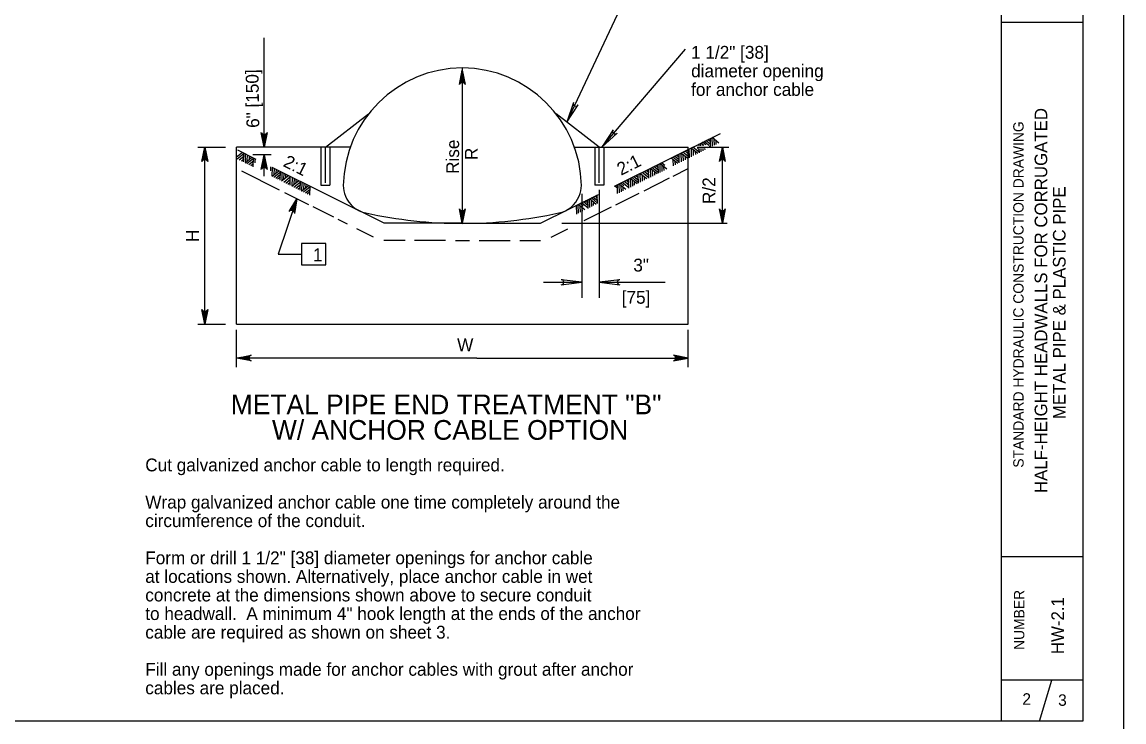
# Model space of a CAD drawing. Extents: x 1083.1 to 1117.1, y 675.4 to 741.4.
# Drawn here: x 1103.72 to 1117.13, y 697.84 to 706.36 of the extents above; entities that cross this region are included whole.
import ezdxf

# ---------------------------------------------------------------- set-up
doc = ezdxf.new("R2010")
doc.units = 0
doc.layers.add('Level 1', color=7, linetype='Continuous')
doc.layers.add('Level 44', color=7, linetype='Continuous')

msp = doc.modelspace()

# ---------------------------------------------------------------- linework, layer by layer
at = {"layer": 'Level 1'}
for p, q in [((1115.636, 697.854), (1115.636, 718.854)), ((1110.352, 705.14), (1111.104, 706.741)), ((1116.626, 706.354), (1115.636, 706.354)), ((1106.67, 704.838), (1106.67, 706.164)), ((1110.775, 704.838), (1111.792, 706.029)), ((1109.054, 705.612), (1109.079, 705.774)), ((1109.065, 705.618), (1109.079, 705.774)), ((1109.079, 705.8), (1109.079, 704.479)), ((1109.079, 705.62), (1109.079, 705.774)), ((1109.091, 705.619), (1109.079, 705.774)), ((1109.102, 705.613), (1109.079, 705.774)), ((1107.413, 704.838), (1107.938, 705.241)), ((1110.745, 704.838), (1110.22, 705.241)), ((1106.647, 704.998), (1106.67, 704.838)), ((1106.658, 704.993), (1106.67, 704.838)), ((1106.695, 705), (1106.67, 704.838)), ((1106.684, 704.994), (1106.67, 704.838)), ((1106.67, 704.991), (1106.67, 704.838)), ((1110.931, 704.36), (1112.219, 705.004)), ((1105.862, 704.838), (1106.2, 704.838)), ((1105.923, 704.676), (1105.948, 704.838)), ((1105.933, 704.682), (1105.948, 704.838)), ((1105.948, 703.621), (1105.948, 704.838)), ((1105.948, 704.685), (1105.948, 704.838)), ((1105.959, 704.683), (1105.948, 704.838)), ((1105.97, 704.678), (1105.948, 704.838)), ((1106.332, 702.685), (1106.332, 704.838)), ((1107.716, 704.838), (1106.332, 704.838)), ((1107.358, 704.838), (1107.358, 704.375)), ((1107.413, 704.404), (1107.413, 704.838)), ((1107.468, 704.838), (1107.468, 704.375)), ((1110.441, 704.838), (1111.826, 704.838)), ((1110.69, 704.838), (1110.69, 704.375)), ((1110.745, 704.404), (1110.745, 704.838)), ((1110.8, 704.838), (1110.8, 704.375)), ((1111.826, 702.685), (1111.826, 704.838)), ((1111.902, 704.819), (1111.882, 704.836)), ((1111.937, 704.853), (1111.929, 704.859)), ((1111.934, 704.838), (1112.32, 704.838)), ((1111.96, 704.854), (1111.959, 704.875)), ((1112.015, 704.855), (1111.979, 704.884)), ((1111.982, 704.854), (1111.981, 704.882)), ((1112.039, 704.864), (1112, 704.895)), ((1112.005, 704.855), (1112.005, 704.863)), ((1112.079, 704.856), (1112.019, 704.904)), ((1112.099, 704.87), (1112.042, 704.916)), ((1112.098, 704.903), (1112.066, 704.928)), ((1112.1, 704.84), (1112.086, 704.85)), ((1112.099, 704.857), (1112.096, 704.943)), ((1112.1, 704.836), (1112.099, 704.851)), ((1112.199, 704.886), (1112.116, 704.952)), ((1112.121, 704.857), (1112.118, 704.95)), ((1112.121, 704.847), (1112.121, 704.852)), ((1112.145, 704.859), (1112.142, 704.931)), ((1112.168, 704.87), (1112.166, 704.912)), ((1112.217, 704.676), (1112.242, 704.838)), ((1112.227, 704.682), (1112.242, 704.838)), ((1112.242, 704.209), (1112.242, 704.838)), ((1112.242, 704.685), (1112.242, 704.838)), ((1112.253, 704.683), (1112.242, 704.838)), ((1112.264, 704.678), (1112.242, 704.838)), ((1106.332, 704.718), (1106.402, 704.773)), ((1106.342, 704.695), (1106.421, 704.758)), ((1106.573, 704.687), (1106.349, 704.799)), ((1106.367, 704.682), (1106.421, 704.725)), ((1106.419, 704.656), (1106.422, 704.763)), ((1106.437, 704.647), (1106.521, 704.714)), ((1106.44, 704.649), (1106.443, 704.752)), ((1106.459, 704.636), (1106.539, 704.701)), ((1106.464, 704.668), (1106.466, 704.741)), ((1106.489, 704.688), (1106.49, 704.729)), ((1106.753, 704.742), (1106.531, 704.742)), ((1106.537, 704.597), (1106.54, 704.704)), ((1106.56, 704.644), (1106.561, 704.693)), ((1106.645, 704.58), (1106.67, 704.742)), ((1106.655, 704.586), (1106.67, 704.742)), ((1106.67, 704.483), (1106.67, 704.742)), ((1106.67, 704.589), (1106.67, 704.742)), ((1106.681, 704.587), (1106.67, 704.742)), ((1106.692, 704.581), (1106.67, 704.742)), ((1111.702, 704.638), (1111.619, 704.704)), ((1111.679, 704.684), (1111.64, 704.715)), ((1111.717, 704.681), (1111.661, 704.725)), ((1111.717, 704.712), (1111.685, 704.737)), ((1111.718, 704.646), (1111.715, 704.752)), ((1111.821, 704.697), (1111.738, 704.763)), ((1111.744, 704.659), (1111.741, 704.76)), ((1111.844, 704.711), (1111.763, 704.776)), ((1111.769, 704.671), (1111.767, 704.74)), ((1111.842, 704.744), (1111.788, 704.788)), ((1111.793, 704.683), (1111.792, 704.72)), ((1111.841, 704.775), (1111.811, 704.8)), ((1111.844, 704.708), (1111.84, 704.815)), ((1111.944, 704.759), (1111.861, 704.825)), ((1111.868, 704.72), (1111.865, 704.822)), ((1111.892, 704.733), (1111.89, 704.802)), ((1111.963, 704.771), (1111.903, 704.819)), ((1111.918, 704.745), (1111.916, 704.781)), ((1111.962, 704.802), (1111.938, 704.821)), ((1111.963, 704.768), (1111.961, 704.82)), ((1111.984, 704.779), (1111.983, 704.82)), ((1112.008, 704.79), (1112.007, 704.819)), ((1112.031, 704.802), (1112.03, 704.819)), ((1112.062, 704.818), (1112.06, 704.819)), ((1106.392, 704.67), (1106.42, 704.692)), ((1106.482, 704.625), (1106.539, 704.67)), ((1106.505, 704.613), (1106.538, 704.639)), ((1106.751, 704.548), (1106.752, 704.598)), ((1108.128, 703.91), (1106.768, 704.59)), ((1106.768, 704.485), (1106.771, 704.588)), ((1106.792, 704.504), (1106.794, 704.577)), ((1106.817, 704.524), (1106.818, 704.565)), ((1111.347, 704.46), (1111.343, 704.566)), ((1111.447, 704.51), (1111.364, 704.576)), ((1111.371, 704.472), (1111.368, 704.573)), ((1111.466, 704.523), (1111.385, 704.587)), ((1111.465, 704.553), (1111.408, 704.599)), ((1111.464, 704.586), (1111.432, 704.611)), ((1111.466, 704.519), (1111.462, 704.626)), ((1111.565, 704.569), (1111.482, 704.636)), ((1111.487, 704.53), (1111.484, 704.633)), ((1111.542, 704.615), (1111.503, 704.646)), ((1111.511, 704.542), (1111.508, 704.614)), ((1111.534, 704.553), (1111.532, 704.595)), ((1111.642, 704.483), (1111.826, 704.575)), ((1111.648, 704.61), (1111.645, 704.683)), ((1111.67, 704.622), (1111.669, 704.664)), ((1111.718, 704.652), (1111.679, 704.684)), ((1106.855, 704.314), (1106.397, 704.543)), ((1106.765, 704.483), (1106.849, 704.55)), ((1106.787, 704.472), (1106.867, 704.537)), ((1106.81, 704.461), (1106.867, 704.506)), ((1106.833, 704.449), (1106.866, 704.475)), ((1106.865, 704.433), (1106.868, 704.54)), ((1106.881, 704.425), (1106.965, 704.492)), ((1106.886, 704.429), (1106.888, 704.48)), ((1106.888, 704.48), (1106.889, 704.529)), ((1106.907, 704.412), (1106.987, 704.475)), ((1106.909, 704.447), (1106.911, 704.519)), ((1106.932, 704.4), (1106.986, 704.443)), ((1106.933, 704.466), (1106.934, 704.507)), ((1106.984, 704.374), (1106.987, 704.48)), ((1107.006, 704.362), (1107.09, 704.429)), ((1107.009, 704.364), (1107.012, 704.468)), ((1107.034, 704.385), (1107.037, 704.455)), ((1107.058, 704.405), (1107.06, 704.444)), ((1109.079, 704.489), (1109.079, 703.91)), ((1111.104, 704.406), (1111.072, 704.431)), ((1111.105, 704.339), (1111.102, 704.446)), ((1111.205, 704.389), (1111.122, 704.455)), ((1111.127, 704.35), (1111.124, 704.453)), ((1111.182, 704.435), (1111.143, 704.466)), ((1111.151, 704.362), (1111.148, 704.434)), ((1111.22, 704.432), (1111.164, 704.477)), ((1111.221, 704.404), (1111.182, 704.435)), ((1111.219, 704.463), (1111.188, 704.489)), ((1111.221, 704.397), (1111.218, 704.504)), ((1111.324, 704.449), (1111.24, 704.515)), ((1111.247, 704.41), (1111.244, 704.512)), ((1111.346, 704.463), (1111.265, 704.527)), ((1111.272, 704.423), (1111.27, 704.492)), ((1111.29, 704.307), (1111.6, 704.462)), ((1111.345, 704.496), (1111.291, 704.54)), ((1111.296, 704.435), (1111.295, 704.471)), ((1111.344, 704.527), (1111.314, 704.551)), ((1111.395, 704.484), (1111.393, 704.553)), ((1111.42, 704.497), (1111.419, 704.532)), ((1106.956, 704.388), (1106.985, 704.411)), ((1107.03, 704.351), (1107.11, 704.414)), ((1107.055, 704.338), (1107.109, 704.381)), ((1107.08, 704.326), (1107.108, 704.348)), ((1107.107, 704.312), (1107.11, 704.419)), ((1107.125, 704.303), (1107.209, 704.37)), ((1107.128, 704.305), (1107.131, 704.408)), ((1107.147, 704.292), (1107.227, 704.357)), ((1107.152, 704.324), (1107.154, 704.397)), ((1107.171, 704.28), (1107.227, 704.326)), ((1107.177, 704.344), (1107.179, 704.385)), ((1107.193, 704.269), (1107.226, 704.295)), ((1107.225, 704.253), (1107.228, 704.36)), ((1107.358, 704.375), (1107.468, 704.375)), ((1110.8, 704.375), (1110.69, 704.375)), ((1110.745, 704.318), (1110.745, 703.005)), ((1110.967, 704.337), (1110.935, 704.362)), ((1110.968, 704.271), (1110.965, 704.378)), ((1111.068, 704.321), (1110.985, 704.387)), ((1110.99, 704.282), (1110.987, 704.385)), ((1111.045, 704.367), (1111.006, 704.398)), ((1111.014, 704.293), (1111.011, 704.366)), ((1111.105, 704.343), (1111.025, 704.407)), ((1111.036, 704.305), (1111.035, 704.347)), ((1111.104, 704.373), (1111.048, 704.419)), ((1111.173, 704.373), (1111.172, 704.415)), ((1107.211, 704.135), (1106.922, 704.28)), ((1106.988, 704.064), (1107.066, 704.208)), ((1107, 704.066), (1107.066, 704.208)), ((1107.014, 704.064), (1107.066, 704.208)), ((1107.025, 704.058), (1107.066, 704.208)), ((1107.033, 704.049), (1107.066, 704.208)), ((1110.031, 703.91), (1110.734, 704.262)), ((1110.608, 704.094), (1110.527, 704.159)), ((1110.533, 704.268), (1110.533, 703.005)), ((1110.607, 704.125), (1110.551, 704.17)), ((1110.606, 704.157), (1110.575, 704.182)), ((1110.608, 704.091), (1110.605, 704.198)), ((1110.708, 704.14), (1110.624, 704.207)), ((1110.63, 704.102), (1110.627, 704.205)), ((1110.685, 704.187), (1110.646, 704.218)), ((1110.653, 704.113), (1110.651, 704.186)), ((1110.723, 704.184), (1110.667, 704.228)), ((1110.676, 704.125), (1110.675, 704.167)), ((1110.724, 704.155), (1110.685, 704.187)), ((1110.722, 704.215), (1110.691, 704.24)), ((1110.724, 704.149), (1110.721, 704.255)), ((1110.947, 704.135), (1111.231, 704.277)), ((1112.242, 703.91), (1112.242, 704.209)), ((1107.515, 703.984), (1107.264, 704.109)), ((1109.057, 704.07), (1109.079, 703.91)), ((1109.068, 704.065), (1109.079, 703.91)), ((1109.104, 704.072), (1109.079, 703.91)), ((1109.094, 704.066), (1109.079, 703.91)), ((1109.079, 704.063), (1109.079, 703.91)), ((1110.471, 704.022), (1110.468, 704.129)), ((1110.571, 704.072), (1110.488, 704.138)), ((1110.493, 704.033), (1110.49, 704.136)), ((1110.548, 704.118), (1110.509, 704.149)), ((1110.517, 704.045), (1110.514, 704.117)), ((1110.539, 704.056), (1110.538, 704.098)), ((1110.563, 703.944), (1110.894, 704.109)), ((1112.219, 704.07), (1112.242, 703.91)), ((1112.23, 704.065), (1112.242, 703.91)), ((1112.266, 704.072), (1112.242, 703.91)), ((1112.256, 704.066), (1112.242, 703.91)), ((1112.242, 704.063), (1112.242, 703.91)), ((1107.684, 703.899), (1107.571, 703.956)), ((1109.086, 703.91), (1108.128, 703.91)), ((1109.086, 703.91), (1110.031, 703.91)), ((1110.289, 703.91), (1112.301, 703.91)), ((1107.998, 703.742), (1107.797, 703.843)), ((1110.16, 703.742), (1110.362, 703.843)), ((1105.948, 702.685), (1105.948, 703.621)), ((1107.123, 703.665), (1107.123, 703.403)), ((1107.421, 703.665), (1107.123, 703.665)), ((1107.421, 703.403), (1107.421, 703.665)), ((1108.382, 703.702), (1108.126, 703.702)), ((1108.875, 703.702), (1108.496, 703.702)), ((1108.998, 703.702), (1109.166, 703.702)), ((1109.283, 703.702), (1109.662, 703.702)), ((1109.777, 703.702), (1110.032, 703.702)), ((1107.123, 703.403), (1107.421, 703.403)), ((1110.066, 703.193), (1110.533, 703.193)), ((1110.745, 703.193), (1111.546, 703.193)), ((1115.868, 703.06), (1115.868, 703.06)), ((1116.258, 703.067), (1116.258, 703.067)), ((1105.925, 702.845), (1105.948, 702.685)), ((1105.937, 702.84), (1105.948, 702.685)), ((1105.973, 702.847), (1105.948, 702.685)), ((1105.962, 702.841), (1105.948, 702.685)), ((1105.948, 702.838), (1105.948, 702.685)), ((1105.862, 702.685), (1106.2, 702.685)), ((1106.332, 702.685), (1111.826, 702.685)), ((1106.33, 702.614), (1106.33, 702.159)), ((1111.823, 702.614), (1111.823, 702.159)), ((1106.493, 702.293), (1106.332, 702.271)), ((1106.487, 702.282), (1106.332, 702.271)), ((1111.666, 702.293), (1111.826, 702.271)), ((1111.671, 702.282), (1111.826, 702.271)), ((1109.255, 702.271), (1106.332, 702.271)), ((1106.486, 702.271), (1106.332, 702.271)), ((1106.488, 702.257), (1106.332, 702.271)), ((1106.495, 702.246), (1106.332, 702.271)), ((1109.255, 702.271), (1111.826, 702.271)), ((1111.664, 702.246), (1111.826, 702.271)), ((1111.67, 702.257), (1111.826, 702.271)), ((1111.673, 702.271), (1111.826, 702.271)), ((1116.626, 699.854), (1115.636, 699.854)), ((1116.626, 698.354), (1115.636, 698.354)), ((1116.101, 697.854), (1116.251, 698.354))]:
    msp.add_line(p, q, dxfattribs=at)
for points in [[(1083.126, 697.354), (1117.126, 697.354), (1117.126, 719.354), (1083.126, 719.354)], [(1083.126, 697.354), (1117.126, 697.354), (1117.126, 719.354), (1083.126, 719.354)], [(1085.126, 718.854), (1116.626, 718.854), (1116.626, 697.854), (1085.126, 697.854)]]:
    msp.add_lwpolyline(points, close=True, dxfattribs=at)
for points in [[(1109.044, 705.597), (1109.079, 705.774), (1109.115, 705.597)], [(1106.705, 705.015), (1106.67, 704.838), (1106.634, 705.015)], [(1105.912, 704.661), (1105.948, 704.838), (1105.983, 704.661)], [(1112.206, 704.661), (1112.242, 704.838), (1112.277, 704.661)], [(1106.634, 704.565), (1106.67, 704.742), (1106.705, 704.565)], [(1107.066, 704.208), (1106.839, 703.534), (1107.123, 703.534)], [(1106.973, 704.053), (1107.066, 704.208), (1107.04, 704.029)], [(1109.115, 704.087), (1109.079, 703.91), (1109.044, 704.087)], [(1112.277, 704.087), (1112.242, 703.91), (1112.206, 704.087)], [(1105.983, 702.862), (1105.948, 702.685), (1105.912, 702.862)], [(1106.509, 702.236), (1106.332, 702.271), (1106.509, 702.306)], [(1111.649, 702.236), (1111.826, 702.271), (1111.649, 702.306)]]:
    msp.add_lwpolyline(points, dxfattribs=at)
for centre, start, end in [((1109.079, 705.582), 22.0878, 157.9139), ((1106.67, 705.029), 202.0878, 337.9139), ((1105.948, 704.647), 22.0878, 157.9139), ((1106.67, 704.55), 22.0878, 157.9139), ((1112.242, 704.647), 22.0878, 157.9139), ((1107.002, 704.028), 2.2124, 138.0385), ((1109.079, 704.101), 202.0878, 337.9139), ((1112.242, 704.101), 202.0878, 337.9139), ((1105.948, 702.876), 202.0878, 337.9139), ((1106.524, 702.271), 112.0878, 247.9139), ((1111.635, 702.271), 292.0861, 67.9122)]:
    msp.add_arc(centre, 0.0382, start, end, dxfattribs=at)
for centre, major_axis, start_param, end_param in [((1109.084, 704.347), (-1.453, 0), 4.71537, 6.266539), ((1109.075, 704.347), (1.453, 0), 0.016646, 1.567816), ((1108.078, 704.396), (-0.448, 0), 0.055055, 0.354919), ((1110.081, 704.396), (0.448, 0), 5.928267, 6.22813), ((1107.979, 704.378), (-0.35, 0), 0.40505, 1.357703), ((1110.179, 704.378), (0.35, 0), 4.925482, 5.878135), ((1109.068, 709.328), (5.419, 0), 4.496144, 4.714418), ((1109.09, 709.328), (-5.419, 0), 1.568767, 1.787041)]:
    msp.add_ellipse(centre, major_axis=major_axis, ratio=0.999895, start_param=start_param, end_param=end_param, dxfattribs=at)
at = {"layer": 'Level 44'}
for p, q in [((1110.43, 705.379), (1110.352, 705.14)), ((1110.352, 705.14), (1110.487, 705.353)), ((1110.913, 705.048), (1110.775, 704.838)), ((1110.775, 704.838), (1110.961, 705.008)), ((1110.533, 703.193), (1110.283, 703.224)), ((1110.995, 703.224), (1110.745, 703.193)), ((1110.283, 703.162), (1110.533, 703.193)), ((1110.745, 703.193), (1110.995, 703.162))]:
    msp.add_line(p, q, dxfattribs=at)
for centre, start, end in [((1110.459, 705.366), 154.8562, 334.8562), ((1110.937, 705.028), 139.4982, 319.4982), ((1110.283, 703.193), 270, 90), ((1110.995, 703.193), 90, 270)]:
    msp.add_arc(centre, 0.0312, start, end, dxfattribs=at)

# ---------------------------------------------------------------- texts
at = {"layer": 'Level 1'}
for s, height, p in [('1 1/2" [38]', 0.156, (1111.862, 705.912)), ('diameter opening', 0.156, (1111.862, 705.686)), ('for anchor cable', 0.156, (1111.862, 705.46)), ('1', 0.16, (1107.261, 703.446)), ('3"', 0.156, (1111.159, 703.324)), ('[75]', 0.156, (1111.018, 702.932)), ('W', 0.156, (1109.016, 702.353)), ('METAL PIPE END TREATMENT "B"', 0.24, (1106.263, 701.587)), ('W/ ANCHOR CABLE OPTION', 0.24, (1106.764, 701.277)), ('Cut galvanized anchor cable to length required.', 0.156, (1105.223, 700.893)), ('Wrap galvanized anchor cable one time completely around the ', 0.156, (1105.223, 700.441)), ('circumference of the conduit.', 0.156, (1105.223, 700.215)), ('Form or drill 1 1/2" [38] diameter openings for anchor cable', 0.156, (1105.223, 699.763)), ('at locations shown. Alternatively, place anchor cable in wet', 0.156, (1105.223, 699.537)), ('concrete at the dimensions shown above to secure conduit ', 0.156, (1105.223, 699.311)), ('to headwall.  A minimum 4" hook length at the ends of the anchor', 0.156, (1105.223, 699.085)), ('cable are required as shown on sheet 3.', 0.156, (1105.223, 698.859)), ('Fill any openings made for anchor cables with grout after anchor', 0.156, (1105.223, 698.407)), ('cables are placed.', 0.156, (1105.223, 698.181)), ('2', 0.14, (1115.891, 698.054)), ('3', 0.14, (1116.326, 698.041))]:
    msp.add_text(s, height=height, dxfattribs=at).set_placement(p)
for s, height, rotation, p in [('6" [150]', 0.156, 90.8499, (1106.61, 705.072)), ('HALF-HEIGHT HEADWALLS FOR CORRUGATED', 0.153, 90, (1116.193, 700.629)), ('STANDARD HYDRAULIC CONSTRUCTION DRAWING', 0.126, 90, (1115.906, 700.938)), ('Rise', 0.156, 90, (1109.04, 704.511)), ('2:1', 0.156, 333.4374, (1106.889, 704.609)), ('R', 0.156, 90, (1109.266, 704.679)), ('2:1', 0.156, 26.5626, (1111.009, 704.487)), ('R/2', 0.156, 90, (1112.157, 704.145)), ('METAL PIPE & PLASTIC PIPE', 0.153, 90, (1116.416, 701.528)), ('H', 0.156, 90, (1105.876, 703.681)), ('NUMBER', 0.126, 90, (1115.915, 698.721)), ('HW-2.1', 0.153, 90, (1116.396, 698.67))]:
    msp.add_text(s, height=height, rotation=rotation, dxfattribs=at).set_placement(p)

doc.saveas('drawing.dxf')
